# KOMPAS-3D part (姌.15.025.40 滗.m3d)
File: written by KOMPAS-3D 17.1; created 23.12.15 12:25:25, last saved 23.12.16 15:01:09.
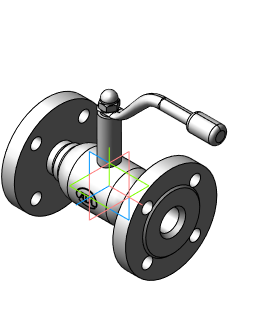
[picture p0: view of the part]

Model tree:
1. Операция без истории:3  (labels: Сталь 20  ГОСТ 1050-88)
